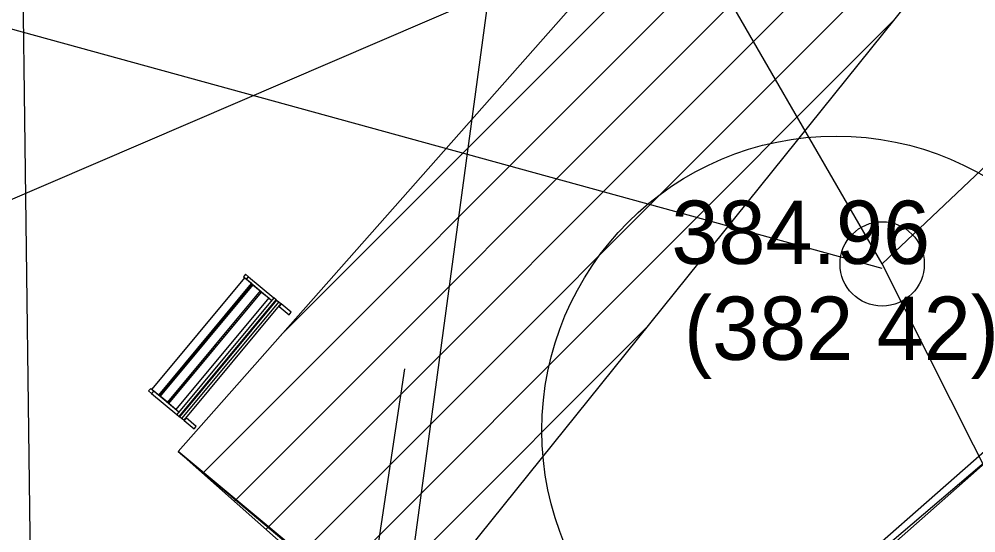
# Model space of a CAD drawing. Extents: x -438233 to -437334, y -1133133 to -1132623.
# Drawn here: x -438087.09 to -438075.74, y -1133013.03 to -1133006.94 of the extents above; entities that cross this region are included whole.
import ezdxf

# ---------------------------------------------------------------- set-up
doc = ezdxf.new("R2010")
doc.units = 0
for name, color, linetype in [('MOBILIÁŘ', 7, 'Continuous'), ('Vrstva 1', 7, 'Continuous'), ('Vrstva 11', 7, 'Continuous'), ('Vrstva 27', 7, 'Continuous'), ('Vrstva 3', 7, 'Continuous'), ('Vrstva 40', 7, 'Continuous'), ('Vrstva 55', 7, 'Continuous'), ('Vrstva 58', 7, 'Continuous')]:
    doc.layers.add(name, color=color, linetype=linetype)

# ---------------------------------------------------------------- blocks, each defined once
blk = doc.blocks.new('A$C6FF56919')
at = {"layer": 'Vrstva 1'}
for p, q in [((-17605, 5482), (-17605, 7031)), ((-401, 7031), (-401, 5482)), ((0, 7031), (-401, 7031)), ((0, 5482), (0, 7031)), ((-18000, 5423), (-18000, 5482)), ((-18000, 5482), (-17605, 5482)), ((-18000, 5423), (0, 5423)), ((-18000, 5108), (-18000, 5423)), ((-18000, 5108), (0, 5108)), ((-18000, 4771), (-18000, 5108)), ((-18000, 4771), (0, 4771)), ((-18000, 4707), (-18000, 4771)), ((0, 4707), (-18000, 4707)), ((-18000, 4707), (-18000, 4365)), ((-17605, 5423), (-17605, 5482)), ((-401, 5482), (0, 5482)), ((-401, 5423), (-401, 5482)), ((0, 5423), (0, 5482)), ((0, 5423), (0, 5108)), ((0, 5108), (0, 4771)), ((0, 4771), (0, 4707)), ((0, 4365), (0, 4707)), ((-18000, 459), (-18000, 4365)), ((-18000, 4365), (0, 4365)), ((-17605, 459), (-17605, 4365)), ((-17605, 3703), (-17594, 3703)), ((-17594, 2805), (-17594, 3895)), ((-401, 3703), (-411, 3703)), ((-401, 459), (-401, 4365)), ((0, 459), (0, 4365)), ((-17605, 2907), (-17594, 2907)), ((-17605, 2901), (-17594, 2901)), ((-17605, 2410), (-17594, 2410)), ((-411, 2805), (-17594, 2805)), ((-17594, 2805), (-17594, 2762)), ((-17594, 2762), (-411, 2762)), ((-17594, 2575), (-411, 2575)), ((-17594, 1475), (-17594, 2575)), ((-9200, 2575), (-9200, 2762)), ((-8799, 2575), (-8799, 2762)), ((-401, 2907), (-411, 2907)), ((-401, 2901), (-411, 2901)), ((-411, 2762), (-411, 2805)), ((-411, 2575), (-411, 1475)), ((-401, 2410), (-411, 2410)), ((-17605, 1608), (-17594, 1608)), ((-17605, 1608), (-17594, 1608)), ((-17594, 1459), (-17594, 1475)), ((-17594, 1475), (-411, 1475)), ((-411, 1459), (-17594, 1459)), ((-17594, 1245), (-17594, 1256)), ((-17594, 1256), (-411, 1256)), ((-17594, 1245), (-17594, 144)), ((-411, 1245), (-17594, 1245)), ((-9200, 1256), (-9200, 1459)), ((-8800, 1256), (-8800, 1459)), ((-401, 1608), (-411, 1608)), ((-401, 1608), (-411, 1608)), ((-411, 1475), (-411, 1459)), ((-411, 1256), (-411, 1245)), ((-411, 144), (-411, 1245)), ((-18000, 459), (-18000, 0)), ((-17605, 459), (-18000, 459)), ((-18000, 0), (-17605, 0)), ((-17605, 1106), (-17594, 1106)), ((-17605, 1106), (-17594, 1106)), ((-17605, 0), (-17605, 459)), ((-17605, 305), (-17594, 305)), ((-17594, 144), (-411, 144)), ((-401, 1106), (-411, 1106)), ((-401, 1106), (-411, 1106)), ((-401, 305), (-411, 305)), ((-401, 459), (0, 459)), ((-401, 0), (-401, 459)), ((0, 0), (-401, 0)), ((0, 459), (0, 0))]:
    blk.add_line(p, q, dxfattribs=at)
for points in [[(-17605, 7031), (-18000, 7031), (-18000, 5482)], [(-17594, 3895), (-411, 3895), (-411, 2805)]]:
    blk.add_lwpolyline(points, dxfattribs=at)

msp = doc.modelspace()

# ---------------------------------------------------------------- linework, layer by layer
at = {"layer": 'Vrstva 1'}
msp.add_line((-438076.856, -1133009.846), (-438076.856, -1133009.846), dxfattribs=at)
at = {"layer": 'Vrstva 11'}
for points in [[(-438079.851, -1133001.541), (-438081.143, -1133003.836), (-438082.651, -1133014.98), (-438080.295, -1133016.157), (-438070.78, -1133008.056), (-438059.123, -1132997.555), (-438044.087, -1132984.346), (-438028.394, -1132970.577), (-438016.298, -1132960.009), (-438006.567, -1132951.363)], [(-438086.925, -1133015.819), (-438087.054, -1133005.669)]]:
    msp.add_lwpolyline(points, dxfattribs=at)
at = {"layer": 'Vrstva 27'}
msp.add_circle((-438076.856, -1133009.846), 0.5, dxfattribs=at)
at = {"layer": 'Vrstva 40'}
for p, q in [((-438083.983, -1133010.687), (-438078.459, -1133005.164)), ((-438084.917, -1133012.328), (-438078.075, -1133005.486)), ((-438084.541, -1133012.66), (-438077.69, -1133005.808)), ((-438084.166, -1133012.992), (-438077.305, -1133006.131)), ((-438083.791, -1133013.324), (-438076.92, -1133006.453)), ((-438083.416, -1133013.656), (-438076.708, -1133006.948)), ((-438083.041, -1133013.988), (-438079.621, -1133010.568)), ((-438086.346, -1133036.484), (-438082.516, -1133011.089)), ((-438085.207, -1133012.071), (-438082.737, -1133014.144))]:
    msp.add_line(p, q, dxfattribs=at)
for points in [[(-438006.567, -1132951.363), (-438080.295, -1133016.157), (-438085.207, -1133012.071), (-438080.546, -1133006.803), (-438077.182, -1133006.231), (-438076.556, -1133006.759), (-438075.914, -1133005.992), (-438066.402, -1132994.506), (-438073.034, -1132988.817), (-438072.353, -1132988.023), (-438069.665, -1132990.252), (-438068.287, -1132988.606), (-438065.604, -1132990.854), (-438063.799, -1132988.701), (-438061.117, -1132990.948), (-438050.796, -1132978.629), (-438047.72, -1132977.59), (-438045.204, -1132976.394), (-438042.678, -1132974.884), (-438040.928, -1132973.634), (-438039.59, -1132972.514), (-438037.876, -1132970.87), (-438035.397, -1132967.806), (-438020.007, -1132954.124)], [(-438082.496, -1133001.782), (-438084.131, -1133003.626), (-438080.546, -1133006.803), (-438085.207, -1133012.071)]]:
    msp.add_lwpolyline(points, dxfattribs=at)
msp.add_lwpolyline([(-438082.496, -1133001.782), (-438084.131, -1133003.626), (-438080.546, -1133006.803), (-438085.207, -1133012.071), (-438082.651, -1133014.333), (-438076.556, -1133006.759)], close=True, dxfattribs=at)
msp.add_circle((-438077.403, -1133011.819), 3.489, dxfattribs=at)
at = {"layer": 'Vrstva 55'}
for points in [[(-437982.978, -1132924.484), (-438038.365, -1132973.439), (-438076.856, -1133009.846)], [(-438074.959, -1133013.61), (-438076.856, -1133009.846), (-438083.298, -1132998.719), (-438115.192, -1132972.054), (-438146.469, -1132953.711), (-438176.9, -1132931.48)], [(-437979.821, -1132940.76), (-437988.363, -1132937.437), (-438041.643, -1132982.184), (-438086.636, -1133021.919)], [(-438092.81, -1133005.512), (-438076.859, -1133009.896)]]:
    msp.add_lwpolyline(points, dxfattribs=at)
at = {"layer": 'Vrstva 58'}
msp.add_lwpolyline([(-438130.562, -1132992.413), (-438128.998, -1132990.895), (-438101.316, -1133015.148), (-438080.005, -1133005.995)], dxfattribs=at)

# ---------------------------------------------------------------- block references
at = {"layer": 'MOBILIÁŘ', "xscale": 9.999999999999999e-05, "yscale": 9.999999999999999e-05, "rotation": -129.77331329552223}
msp.add_blockref('A$C6FF56919', (-438085.557, -1133011.352), dxfattribs=at)

# ---------------------------------------------------------------- texts
at = {"layer": 'Vrstva 3'}
msp.add_text('384.96 ', height=0.75, dxfattribs=at).set_placement((-438079.356, -1133009.846))
at = {"layer": 'Vrstva 55'}
msp.add_text('(382 42) ', height=0.75, dxfattribs=at).set_placement((-438079.207, -1133010.983))

doc.saveas('drawing.dxf')
